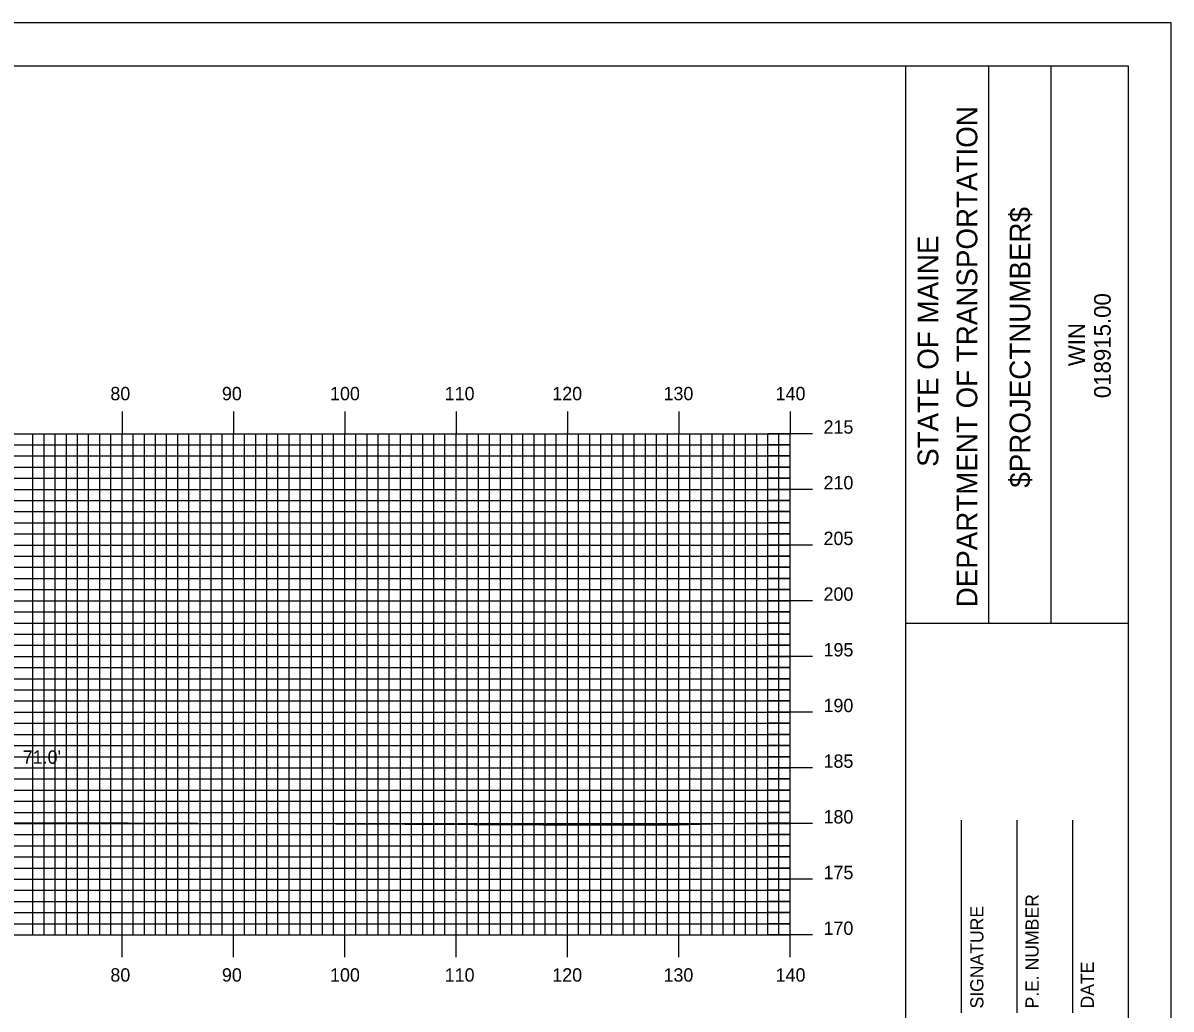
# Model space of a CAD drawing. Extents: x 1809406 to 1809749, y 442591 to 442811.
# Drawn here: x 1809642.9 to 1809746.1, y 442722 to 442810.5 of the extents above; entities that cross this region are included whole.
import ezdxf

# ---------------------------------------------------------------- set-up
doc = ezdxf.new("R2010")
doc.units = 0
for name, color, linetype in [('BORDER', 7, 'Continuous'), ('D_Text_Standard', 7, 'Continuous'), ('H_V ANNOTATION', 7, 'Continuous'), ('MAJOR', 7, 'Continuous'), ('MINOR', 7, 'Continuous'), ('PLOT BOUNDARY', 7, 'Continuous'), ('S_Roadway_Centerline', 7, 'Continuous')]:
    doc.layers.add(name, color=color, linetype=linetype)

msp = doc.modelspace()

# ---------------------------------------------------------------- linework, layer by layer
at = {"layer": 'BORDER'}
for p, q in [((1809722.24, 442596.67), (1809722.24, 442806.67)), ((1809729.69, 442756.66), (1809729.69, 442806.66)), ((1809735.28, 442756.66), (1809735.28, 442806.66)), ((1809722.24, 442756.65), (1809742.24, 442756.65)), ((1809727.24, 442721.67), (1809727.24, 442738.97)), ((1809732.24, 442721.67), (1809732.24, 442738.97)), ((1809737.24, 442721.67), (1809737.24, 442738.97))]:
    msp.add_line(p, q, dxfattribs=at)
msp.add_lwpolyline([(1809422.24, 442596.67), (1809742.24, 442596.67), (1809742.24, 442806.67), (1809422.24, 442806.67)], close=True, dxfattribs=at)
at = {"layer": 'MAJOR'}
for p, q in [((1809651.84, 442775.67), (1809651.84, 442773.67)), ((1809661.84, 442775.67), (1809661.84, 442773.67)), ((1809671.84, 442775.67), (1809671.84, 442773.67)), ((1809681.84, 442775.67), (1809681.84, 442773.67)), ((1809691.84, 442775.67), (1809691.84, 442773.67)), ((1809701.84, 442775.67), (1809701.84, 442773.67)), ((1809711.84, 442775.67), (1809711.84, 442773.67)), ((1809431.84, 442773.67), (1809711.84, 442773.67)), ((1809431.84, 442773.67), (1809711.84, 442773.67)), ((1809651.84, 442728.67), (1809651.84, 442773.67)), ((1809661.84, 442728.67), (1809661.84, 442773.67)), ((1809671.84, 442728.67), (1809671.84, 442773.67)), ((1809681.84, 442728.67), (1809681.84, 442773.67)), ((1809691.84, 442728.67), (1809691.84, 442773.67)), ((1809701.84, 442728.67), (1809701.84, 442773.67)), ((1809713.84, 442773.67), (1809709.83, 442773.67)), ((1809711.84, 442728.67), (1809711.84, 442773.67)), ((1809711.84, 442728.67), (1809711.84, 442773.67)), ((1809431.84, 442768.67), (1809711.84, 442768.67)), ((1809713.84, 442768.67), (1809709.83, 442768.67)), ((1809431.84, 442763.67), (1809711.84, 442763.67)), ((1809713.84, 442763.67), (1809709.83, 442763.67)), ((1809431.84, 442758.67), (1809711.84, 442758.67)), ((1809713.84, 442758.67), (1809709.83, 442758.67)), ((1809431.84, 442753.67), (1809711.84, 442753.67)), ((1809713.84, 442753.67), (1809709.83, 442753.67)), ((1809431.84, 442748.67), (1809711.84, 442748.67)), ((1809713.84, 442748.67), (1809709.83, 442748.67)), ((1809431.84, 442743.67), (1809711.84, 442743.67)), ((1809713.84, 442743.67), (1809709.83, 442743.67)), ((1809431.84, 442738.67), (1809711.84, 442738.67)), ((1809713.84, 442738.67), (1809709.83, 442738.67)), ((1809431.84, 442733.67), (1809711.84, 442733.67)), ((1809713.84, 442733.67), (1809709.83, 442733.67)), ((1809431.84, 442728.67), (1809711.84, 442728.67)), ((1809431.84, 442728.67), (1809711.84, 442728.67)), ((1809651.84, 442726.66), (1809651.84, 442728.67)), ((1809661.84, 442726.66), (1809661.84, 442728.67)), ((1809671.84, 442726.66), (1809671.84, 442728.67)), ((1809681.84, 442726.66), (1809681.84, 442728.67)), ((1809691.84, 442726.66), (1809691.84, 442728.67)), ((1809701.84, 442726.66), (1809701.84, 442728.67)), ((1809713.84, 442728.67), (1809709.83, 442728.67)), ((1809711.84, 442726.66), (1809711.84, 442728.67))]:
    msp.add_line(p, q, dxfattribs=at)
at = {"layer": 'MINOR'}
for p, q in [((1809643.84, 442728.67), (1809643.84, 442773.67)), ((1809644.84, 442728.67), (1809644.84, 442773.67)), ((1809645.84, 442728.67), (1809645.84, 442773.67)), ((1809646.84, 442728.67), (1809646.84, 442773.67)), ((1809647.84, 442728.67), (1809647.84, 442773.67)), ((1809648.84, 442728.67), (1809648.84, 442773.67)), ((1809649.84, 442728.67), (1809649.84, 442773.67)), ((1809650.84, 442728.67), (1809650.84, 442773.67)), ((1809652.84, 442728.67), (1809652.84, 442773.67)), ((1809653.84, 442728.67), (1809653.84, 442773.67)), ((1809654.84, 442728.67), (1809654.84, 442773.67)), ((1809655.84, 442728.67), (1809655.84, 442773.67)), ((1809656.84, 442728.67), (1809656.84, 442773.67)), ((1809657.84, 442728.67), (1809657.84, 442773.67)), ((1809658.84, 442728.67), (1809658.84, 442773.67)), ((1809659.84, 442728.67), (1809659.84, 442773.67)), ((1809660.84, 442728.67), (1809660.84, 442773.67)), ((1809662.84, 442728.67), (1809662.84, 442773.67)), ((1809663.84, 442728.67), (1809663.84, 442773.67)), ((1809664.84, 442728.67), (1809664.84, 442773.67)), ((1809665.84, 442728.67), (1809665.84, 442773.67)), ((1809666.84, 442728.67), (1809666.84, 442773.67)), ((1809667.84, 442728.67), (1809667.84, 442773.67)), ((1809668.84, 442728.67), (1809668.84, 442773.67)), ((1809669.84, 442728.67), (1809669.84, 442773.67)), ((1809670.84, 442728.67), (1809670.84, 442773.67)), ((1809672.84, 442728.67), (1809672.84, 442773.67)), ((1809673.84, 442728.67), (1809673.84, 442773.67)), ((1809674.84, 442728.67), (1809674.84, 442773.67)), ((1809675.84, 442728.67), (1809675.84, 442773.67)), ((1809676.84, 442728.67), (1809676.84, 442773.67)), ((1809677.84, 442728.67), (1809677.84, 442773.67)), ((1809678.84, 442728.67), (1809678.84, 442773.67)), ((1809679.84, 442728.67), (1809679.84, 442773.67)), ((1809680.84, 442728.67), (1809680.84, 442773.67)), ((1809682.84, 442728.67), (1809682.84, 442773.67)), ((1809683.84, 442728.67), (1809683.84, 442773.67)), ((1809684.84, 442728.67), (1809684.84, 442773.67)), ((1809685.84, 442728.67), (1809685.84, 442773.67)), ((1809686.84, 442728.67), (1809686.84, 442773.67)), ((1809687.84, 442728.67), (1809687.84, 442773.67)), ((1809688.84, 442728.67), (1809688.84, 442773.67)), ((1809689.84, 442728.67), (1809689.84, 442773.67)), ((1809690.84, 442728.67), (1809690.84, 442773.67)), ((1809692.84, 442728.67), (1809692.84, 442773.67)), ((1809693.84, 442728.67), (1809693.84, 442773.67)), ((1809694.84, 442728.67), (1809694.84, 442773.67)), ((1809695.84, 442728.67), (1809695.84, 442773.67)), ((1809696.84, 442728.67), (1809696.84, 442773.67)), ((1809697.84, 442728.67), (1809697.84, 442773.67)), ((1809698.84, 442728.67), (1809698.84, 442773.67)), ((1809699.84, 442728.67), (1809699.84, 442773.67)), ((1809700.84, 442728.67), (1809700.84, 442773.67)), ((1809702.84, 442728.67), (1809702.84, 442773.67)), ((1809703.84, 442728.67), (1809703.84, 442773.67)), ((1809704.84, 442728.67), (1809704.84, 442773.67)), ((1809705.84, 442728.67), (1809705.84, 442773.67)), ((1809706.84, 442728.67), (1809706.84, 442773.67)), ((1809707.84, 442728.67), (1809707.84, 442773.67)), ((1809708.84, 442728.67), (1809708.84, 442773.67)), ((1809709.84, 442728.67), (1809709.84, 442773.67)), ((1809710.84, 442728.67), (1809710.84, 442773.67)), ((1809431.84, 442772.67), (1809711.84, 442772.67)), ((1809711.84, 442772.67), (1809709.83, 442772.67)), ((1809431.84, 442771.67), (1809711.84, 442771.67)), ((1809711.84, 442771.67), (1809709.83, 442771.67)), ((1809431.84, 442770.67), (1809711.84, 442770.67)), ((1809711.84, 442770.67), (1809709.83, 442770.67)), ((1809431.84, 442769.67), (1809711.84, 442769.67)), ((1809711.84, 442769.67), (1809709.83, 442769.67)), ((1809431.84, 442767.67), (1809711.84, 442767.67)), ((1809711.84, 442767.67), (1809709.83, 442767.67)), ((1809431.84, 442766.67), (1809711.84, 442766.67)), ((1809711.84, 442766.67), (1809709.83, 442766.67)), ((1809431.84, 442765.67), (1809711.84, 442765.67)), ((1809711.84, 442765.67), (1809709.83, 442765.67)), ((1809431.84, 442764.67), (1809711.84, 442764.67)), ((1809711.84, 442764.67), (1809709.83, 442764.67)), ((1809431.84, 442762.67), (1809711.84, 442762.67)), ((1809711.84, 442762.67), (1809709.83, 442762.67)), ((1809431.84, 442761.67), (1809711.84, 442761.67)), ((1809711.84, 442761.67), (1809709.83, 442761.67)), ((1809431.84, 442760.67), (1809711.84, 442760.67)), ((1809431.84, 442759.67), (1809711.84, 442759.67)), ((1809711.84, 442760.67), (1809709.83, 442760.67)), ((1809711.84, 442759.67), (1809709.83, 442759.67)), ((1809431.84, 442757.67), (1809711.84, 442757.67)), ((1809711.84, 442757.67), (1809709.83, 442757.67)), ((1809431.84, 442756.67), (1809711.84, 442756.67)), ((1809711.84, 442756.67), (1809709.83, 442756.67)), ((1809431.84, 442755.67), (1809711.84, 442755.67)), ((1809711.84, 442755.67), (1809709.83, 442755.67)), ((1809431.84, 442754.67), (1809711.84, 442754.67)), ((1809711.84, 442754.67), (1809709.83, 442754.67)), ((1809431.84, 442752.67), (1809711.84, 442752.67)), ((1809711.84, 442752.67), (1809709.83, 442752.67)), ((1809431.84, 442751.67), (1809711.84, 442751.67)), ((1809711.84, 442751.67), (1809709.83, 442751.67)), ((1809431.84, 442750.67), (1809711.84, 442750.67)), ((1809711.84, 442750.67), (1809709.83, 442750.67)), ((1809431.84, 442749.67), (1809711.84, 442749.67)), ((1809711.84, 442749.67), (1809709.83, 442749.67)), ((1809431.84, 442747.67), (1809711.84, 442747.67)), ((1809711.84, 442747.67), (1809709.83, 442747.67)), ((1809431.84, 442746.67), (1809711.84, 442746.67)), ((1809711.84, 442746.67), (1809709.83, 442746.67)), ((1809431.84, 442745.67), (1809711.84, 442745.67)), ((1809711.84, 442745.67), (1809709.83, 442745.67)), ((1809431.84, 442744.67), (1809711.84, 442744.67)), ((1809711.84, 442744.67), (1809709.83, 442744.67)), ((1809431.84, 442742.67), (1809711.84, 442742.67)), ((1809711.84, 442742.67), (1809709.83, 442742.67)), ((1809431.84, 442741.67), (1809711.84, 442741.67)), ((1809711.84, 442741.67), (1809709.83, 442741.67)), ((1809431.84, 442740.67), (1809711.84, 442740.67)), ((1809711.84, 442740.67), (1809709.83, 442740.67)), ((1809431.84, 442739.67), (1809711.84, 442739.67)), ((1809711.84, 442739.67), (1809709.83, 442739.67)), ((1809431.84, 442737.67), (1809711.84, 442737.67)), ((1809711.84, 442737.67), (1809709.83, 442737.67)), ((1809431.84, 442736.67), (1809711.84, 442736.67)), ((1809711.84, 442736.67), (1809709.83, 442736.67)), ((1809431.84, 442735.67), (1809711.84, 442735.67)), ((1809711.84, 442735.67), (1809709.83, 442735.67)), ((1809431.84, 442734.67), (1809711.84, 442734.67)), ((1809711.84, 442734.67), (1809709.83, 442734.67)), ((1809431.84, 442732.67), (1809711.84, 442732.67)), ((1809711.84, 442732.67), (1809709.83, 442732.67)), ((1809431.84, 442731.67), (1809711.84, 442731.67)), ((1809711.84, 442731.67), (1809709.83, 442731.67)), ((1809431.84, 442730.67), (1809711.84, 442730.67)), ((1809711.84, 442730.67), (1809709.83, 442730.67)), ((1809431.84, 442729.67), (1809711.84, 442729.67)), ((1809711.84, 442729.67), (1809709.83, 442729.67))]:
    msp.add_line(p, q, dxfattribs=at)
at = {"layer": 'PLOT BOUNDARY'}
msp.add_lwpolyline([(1809406.05, 442590.55), (1809746.05, 442590.55), (1809746.05, 442810.55), (1809406.05, 442810.55)], close=True, dxfattribs=at)
at = {"layer": 'S_Roadway_Centerline'}
msp.add_lwpolyline([(1809431.84, 442738.37), (1809434.29, 442738.36), (1809434.65, 442738.3), (1809452.6, 442737.8), (1809467.85, 442737.87), (1809488.36, 442738.44), (1809500.77, 442738.32), (1809523.64, 442738.26), (1809548.73, 442738.59), (1809580.88, 442738.83), (1809599.23, 442738.79), (1809626.5, 442738.72), (1809646.18, 442738.75), (1809689.65, 442738.55), (1809701.87, 442738.54), (1809705.77, 442738.66), (1809711.84, 442738.76)], dxfattribs=at)

# ---------------------------------------------------------------- texts
at = {"layer": 'BORDER'}
for s, height, p in [('DEPARTMENT OF TRANSPORTATION', 1.8635, (1809728.65, 442758.08)), ('$PROJECTNUMBER$', 1.8635, (1809733.42, 442768.82)), ('STATE OF MAINE', 1.8635, (1809725.15, 442770.69)), ('018915.00', 1.491, (1809740.63, 442776.86)), ('WIN', 1.491, (1809738.31, 442779.73)), ('P.E. NUMBER', 1.1811, (1809734.16, 442722.06)), ('SIGNATURE', 1.181, (1809729.2, 442722.06)), ('DATE', 1.181, (1809739.12, 442722.06))]:
    msp.add_text(s, height=height, rotation=90, dxfattribs=at).set_placement(p)
at = {"layer": 'D_Text_Standard'}
msp.add_text("71.0'", height=1.2, dxfattribs=at).set_placement((1809642.92, 442744.03))
at = {"layer": 'H_V ANNOTATION'}
for s, p in [('80', (1809650.79, 442776.67)), ('90', (1809660.81, 442776.67)), ('100', (1809670.52, 442776.67)), ('110', (1809680.82, 442776.67)), ('120', (1809690.48, 442776.67)), ('130', (1809700.47, 442776.67)), ('140', (1809710.54, 442776.67)), ('215', (1809714.84, 442773.67)), ('210', (1809714.84, 442768.67)), ('205', (1809714.84, 442763.67)), ('200', (1809714.84, 442758.67)), ('195', (1809714.84, 442753.67)), ('190', (1809714.84, 442748.67)), ('185', (1809714.84, 442743.67)), ('180', (1809714.84, 442738.67)), ('175', (1809714.84, 442733.67)), ('170', (1809714.84, 442728.67)), ('80', (1809650.79, 442724.47)), ('90', (1809660.81, 442724.47)), ('100', (1809670.52, 442724.47)), ('110', (1809680.82, 442724.47)), ('120', (1809690.48, 442724.47)), ('130', (1809700.47, 442724.47)), ('140', (1809710.54, 442724.47))]:
    msp.add_text(s, height=1.2, dxfattribs=at).set_placement(p)

doc.saveas('drawing.dxf')
